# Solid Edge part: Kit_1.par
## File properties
Sűrűség: 0,000 kg/m^3
Pontosság: 0,990
Author: ahadarics
Last saved by: ahadarics
Revision: 76
Username: ahadarics
Dokumentum tartalom típus: 0
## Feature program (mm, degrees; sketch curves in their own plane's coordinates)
base feature "unnamed BaseFeature 1"
sketch for "unnamed Hole 1" plane through (44.5, -44.5, -94.5) normal (0, 0, -1) x-axis (0, 1, 0)
  hole centre (0, 0) bore radius 4.188
hole "unnamed Hole 1" through
sketch for "unnamed Hole 2" plane through (44.5, -44.5, -94.5) normal (0, 0, -1) x-axis (0, 1, 0)
  hole centre (89, 0) bore radius 4.188
hole "unnamed Hole 2" through
sketch for "unnamed Hole 3" plane through (44.5, -44.5, -94.5) normal (0, 0, -1) x-axis (0, 1, 0)
  hole centre (0, -89) bore radius 4.188
hole "unnamed Hole 3" through
sketch for "unnamed Hole 4" plane through (44.5, -44.5, -94.5) normal (0, 0, -1) x-axis (0, 1, 0)
  hole centre (89, -89) bore radius 4.188
hole "unnamed Hole 4" through
pattern "unnamed Pattern 1" of "unnamed Hole 1", "unnamed Hole 2", "unnamed Hole 3", "unnamed Hole 4"
sketch for "Furat_5" plane through (56.5649, 0, -87.75) normal (0.999962, 0, -0.008727) x-axis (0, 1, 0)
  hole centre (-0.0002, 0.7496) bore radius 4.283
hole "Furat_5" diameter 8.566 finite
thread "unnamed Thread 1"
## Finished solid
Body 1: solid body, 320 faces, 800 edges, 501 vertices.
  Faces by surface: plane 145, cylinder 82, swept 56, cone 25, torus 11, spline 1
  Edges by curve: line 446, circle 180, spline 136, ellipse 28, curve on surface 10
Bounding box of the edges (mm; curved faces can reach further): 113.300 x 113.300 x 19.500, from (-56.65, -56.65, -97.5) to (56.65, 56.65, -78).
Cylindrical faces by radius (mm): R0.2 x48, R0.2006 x2, R0.2007 x2, R4.188 x4, R4.283 x1, R6.35 x4, R6.55 x4, R6.75 x4, R12.8 x1, R13.45 x1, R14 x1, R14.9 x1, R15 x1, R51.85 x8
Conical faces (half-angle, radius in mm at the cone's reference point): 0.5 deg R12.25 x4, 0.5 deg R35 x2, 3 deg R14.95 x1, 7 deg R14.2695 x1, 14 deg R12.65 x1, 14 deg R13.057 x1, 17 deg R12.65 x1, 23 deg R13.4211 x1, 42.5 deg R12.637 x1, 45 deg R4.185 x4, 45 deg R4.985 x4, 45 deg R13.6 x1, 84 deg R13.012 x1, 85 deg R14.6625 x1, 87 deg R12.7157 x1
Toroidal faces (ring radius, tube radius in mm): R6.05 r0.3 x2, R6.15 r0.2 x6, R13.4008 r0.225 x1, R13.8914 r0.325 x1, R14.7 r0.2 x1
Planar faces by outward normal: +x 16, +y 14, +z 2, -x 14, -y 16, -z 19, oblique 64
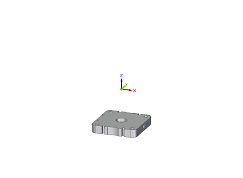
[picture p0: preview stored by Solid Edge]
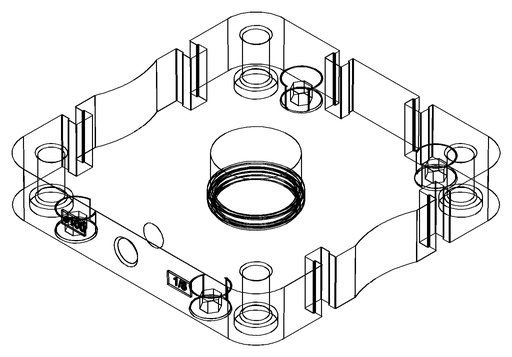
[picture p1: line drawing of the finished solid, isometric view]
